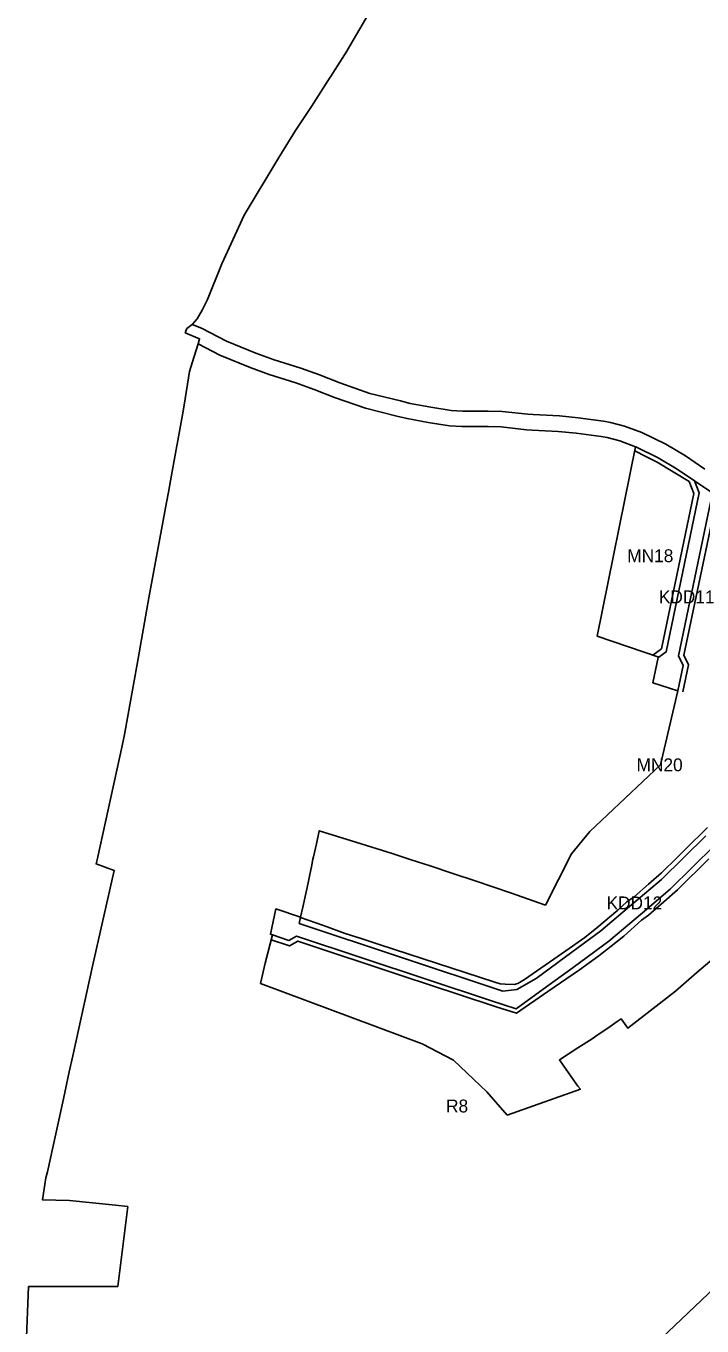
# Model space of a CAD drawing. Extents: x 7439486 to 7443435, y 5551288 to 5554556.
# Drawn here: x 7439611 to 7440135, y 5551897 to 5552904 of the extents above; entities that cross this region are included whole.
import ezdxf

# ---------------------------------------------------------------- set-up
doc = ezdxf.new("R2010")
doc.units = 0
for name, color, linetype in [('linie_rozgraniczajace', 7, 'Continuous'), ('linie_zabudowy_nieprzekraczalne', 7, 'Continuous'), ('oznaczenia_przeznaczen', 7, 'Continuous')]:
    doc.layers.add(name, color=color, linetype=linetype)

msp = doc.modelspace()

# ---------------------------------------------------------------- linework, layer by layer
at = {"layer": 'linie_rozgraniczajace'}
for points in [[(7439847.01, 5552864.42), (7439859.69, 5552884.24), (7439864.7, 5552892.84), (7439864.72, 5552892.88), (7439879.41, 5552917.8)], [(7440136.75, 5552560.73), (7440121.83, 5552570.88), (7440106.57, 5552579.91), (7440088.11, 5552589.02), (7440074.72, 5552593.93), (7440063.78, 5552596.91), (7440058.54, 5552597.78), (7440038.73, 5552600.51), (7440024.24, 5552601.88), (7440003.94, 5552602.96), (7439999.88, 5552603.17), (7439979.98, 5552605.4), (7439969.18, 5552605.67), (7439949.17, 5552605.61), (7439940.51, 5552606.18), (7439924.74, 5552608.72), (7439908.84, 5552611.58), (7439901.28, 5552613.47), (7439877.57, 5552619.38), (7439854.38, 5552627.4), (7439838.6, 5552633.66), (7439824.12, 5552638.78), (7439803.55, 5552645.29), (7439789.3, 5552650.49), (7439766.62, 5552659.73), (7439747.13, 5552669.92), (7439740.09, 5552672.71), (7439740.25, 5552672.84), (7439743.95, 5552677.01), (7439747.68, 5552683.73), (7439751.79, 5552692.12), (7439762.9, 5552719.61), (7439780.21, 5552757.37), (7439807.09, 5552802.1), (7439820.12, 5552822.79), (7439832.42, 5552841.4), (7439846.87, 5552864.2), (7439847.01, 5552864.42)], [(7439734.52, 5552666.24), (7439735.82, 5552669.57), (7439740.09, 5552672.71), (7439747.13, 5552669.92), (7439766.62, 5552659.73), (7439789.3, 5552650.49), (7439803.55, 5552645.29), (7439824.12, 5552638.78), (7439838.6, 5552633.66), (7439854.38, 5552627.4), (7439877.57, 5552619.38), (7439901.28, 5552613.47), (7439908.84, 5552611.58), (7439924.74, 5552608.72), (7439940.51, 5552606.18), (7439949.17, 5552605.61), (7439969.18, 5552605.67), (7439979.98, 5552605.4), (7439999.88, 5552603.17), (7440003.94, 5552602.96), (7440024.24, 5552601.88), (7440038.73, 5552600.51), (7440058.54, 5552597.78), (7440063.78, 5552596.91), (7440074.72, 5552593.93), (7440088.11, 5552589.02), (7440106.57, 5552579.91), (7440121.83, 5552570.88), (7440136.75, 5552560.73)], [(7440003.3, 5552590.98), (7439998.89, 5552591.21), (7439979.16, 5552593.42), (7439969.04, 5552593.67), (7439948.79, 5552593.61), (7439939.16, 5552594.24), (7439922.72, 5552596.89), (7439906.32, 5552599.84), (7439898.37, 5552601.83), (7439874.16, 5552607.87), (7439850.21, 5552616.15), (7439834.38, 5552622.42), (7439820.31, 5552627.4), (7439799.69, 5552633.93), (7439784.98, 5552639.29), (7439761.56, 5552648.83), (7439744.57, 5552657.73), (7439745.81, 5552661.68), (7439734.52, 5552666.24)], [(7439611.4, 5551881.93), (7439613.43, 5551927.75), (7439682.55, 5551927.9), (7439690.17, 5551989.77), (7439680.8, 5551990.73), (7439662.93, 5551992.58), (7439645.07, 5551994.44), (7439634.57, 5551994.74), (7439624.07, 5551995.04), (7439626.62, 5552011.92), (7439628.11, 5552016.58), (7439640.32, 5552073.23), (7439644.91, 5552094.13), (7439647.6, 5552106.42), (7439662.83, 5552175.92), (7439679.7, 5552250.02), (7439665.66, 5552255.08), (7439666.38, 5552258.33), (7439685.87, 5552346.55), (7439687.52, 5552355.35), (7439695.23, 5552396.78), (7439697.5, 5552409.68), (7439706.53, 5552461.04), (7439720.23, 5552534.81), (7439721.71, 5552542.98), (7439724.05, 5552555.91), (7439732.52, 5552602.7), (7439733.73, 5552610.29), (7439737.83, 5552636.3), (7439739.94, 5552642.98), (7439744.57, 5552657.73), (7439761.56, 5552648.83), (7439784.98, 5552639.29), (7439799.69, 5552633.93), (7439820.31, 5552627.4), (7439834.38, 5552622.42), (7439850.21, 5552616.15), (7439874.16, 5552607.87), (7439898.37, 5552601.83), (7439906.32, 5552599.84), (7439922.72, 5552596.89), (7439939.16, 5552594.24), (7439948.79, 5552593.61), (7439969.04, 5552593.67), (7439979.16, 5552593.42), (7439998.89, 5552591.21), (7440003.3, 5552590.98), (7440023.35, 5552589.91), (7440037.34, 5552588.59), (7440056.74, 5552585.91), (7440061.21, 5552585.17), (7440071.07, 5552582.48), (7440083.31, 5552578.01), (7440053.45, 5552431.46), (7440101.21, 5552415.17), (7440100.84, 5552414.91), (7440096.73, 5552395.22), (7440115.87, 5552389.07), (7440102.66, 5552331.77), (7440047.9, 5552280.13), (7440033.63, 5552262.97), (7440023.56, 5552243.08), (7440013.5, 5552223.2), (7439986.34, 5552232.6), (7439959.17, 5552241.99), (7439941.77, 5552247.72), (7439924.36, 5552253.44), (7439909.59, 5552258.3), (7439894.81, 5552263.15), (7439866.59, 5552271.96), (7439838.36, 5552280.76), (7439836.16, 5552270.66), (7439833.95, 5552260.55), (7439833.52, 5552258.6), (7439832.28, 5552252.7), (7439831.05, 5552246.79), (7439830, 5552241.8), (7439828.96, 5552236.81), (7439825.6, 5552221.49), (7439823.94, 5552213.92), (7439804.85, 5552220.26), (7439800.54, 5552200.62), (7439802.1, 5552200.1), (7439800.37, 5552193.23), (7439796.55, 5552178.12), (7439792.97, 5552162.52), (7439917.99, 5552115.63), (7439942.23, 5552103.19), (7439968.1, 5552078.48)], [(7440140.66, 5552543.57), (7440128.82, 5552551.62), (7440115.4, 5552560.74), (7440100.85, 5552569.35), (7440083.38, 5552577.98), (7440083.31, 5552578.01), (7440071.07, 5552582.48), (7440061.21, 5552585.17), (7440056.74, 5552585.91), (7440037.34, 5552588.59), (7440023.35, 5552589.91), (7440003.3, 5552590.98)], [(7440137.55, 5552276.9), (7440103.24, 5552242.87), (7440082.02, 5552224.85), (7440056.44, 5552203.12), (7440028.96, 5552183.05), (7440006.17, 5552166.39), (7439991.42, 5552157.79), (7439980.56, 5552156.64), (7439822.86, 5552209.01), (7439823.94, 5552213.92), (7439825.6, 5552221.49), (7439828.96, 5552236.81), (7439830, 5552241.8), (7439831.05, 5552246.79), (7439832.28, 5552252.7), (7439833.52, 5552258.6), (7439833.95, 5552260.55), (7439836.16, 5552270.66), (7439838.36, 5552280.76), (7439866.59, 5552271.96), (7439894.81, 5552263.15), (7439909.59, 5552258.3), (7439924.36, 5552253.44), (7439941.77, 5552247.72), (7439959.17, 5552241.99), (7439986.34, 5552232.6), (7440013.5, 5552223.2), (7440023.56, 5552243.08), (7440033.63, 5552262.97), (7440047.9, 5552280.13), (7440102.66, 5552331.77), (7440115.87, 5552389.07), (7440119.99, 5552408.76), (7440116.42, 5552416.13), (7440141.53, 5552536.28)], [(7439792.97, 5552162.52), (7439796.55, 5552178.12), (7439800.37, 5552193.23), (7439802.1, 5552200.1), (7439814.85, 5552195.86), (7439820.7, 5552199.19), (7439971.81, 5552149.02), (7439990.73, 5552142.73), (7440011.65, 5552158.02), (7440034.86, 5552174.97), (7440062.64, 5552195.27), (7440088.5, 5552217.23), (7440110.01, 5552235.5), (7440144.47, 5552269.69)], [(7440144.47, 5552269.69), (7440110.01, 5552235.5), (7440088.5, 5552217.23), (7440062.64, 5552195.27), (7440034.86, 5552174.97), (7440011.65, 5552158.02), (7439990.73, 5552142.73), (7439971.81, 5552149.02), (7439820.7, 5552199.19), (7439814.85, 5552195.86), (7439802.1, 5552200.1), (7439800.54, 5552200.62), (7439804.85, 5552220.26), (7439823.94, 5552213.92), (7439822.86, 5552209.01), (7439980.56, 5552156.64), (7439991.42, 5552157.79), (7440006.17, 5552166.39), (7440028.96, 5552183.05), (7440056.44, 5552203.12), (7440082.02, 5552224.85), (7440103.24, 5552242.87), (7440137.55, 5552276.9)], [(7439968.1, 5552078.48), (7439983.87, 5552060.52), (7440040.55, 5552080.59), (7440038.52, 5552082.98), (7440033.13, 5552090.69), (7440027.74, 5552098.4), (7440024.32, 5552103.35), (7440038.68, 5552112.6), (7440049.66, 5552119.66), (7440054.38, 5552122.93), (7440061.69, 5552127.98), (7440069.07, 5552133.08), (7440070.59, 5552134.13), (7440072.05, 5552135.14), (7440077.2, 5552127.96), (7440114.09, 5552156.56), (7440130.74, 5552170.86), (7440147.39, 5552185.16)], [(7440147.39, 5552185.16), (7440130.74, 5552170.86), (7440114.09, 5552156.56), (7440077.2, 5552127.96), (7440072.05, 5552135.14), (7440070.59, 5552134.13), (7440069.07, 5552133.08), (7440061.69, 5552127.98), (7440054.38, 5552122.93)], [(7440054.38, 5552122.93), (7440049.66, 5552119.66), (7440038.68, 5552112.6), (7440024.32, 5552103.35), (7440027.74, 5552098.4), (7440033.13, 5552090.69), (7440038.52, 5552082.98), (7440040.55, 5552080.59), (7439983.87, 5552060.52), (7439968.1, 5552078.48), (7439942.23, 5552103.19), (7439917.99, 5552115.63), (7439792.97, 5552162.52)], [(7440170.49, 5551951.58), (7439741.39, 5551543.86)], [(7439741.39, 5551543.86), (7440170.49, 5551951.58)]]:
    msp.add_lwpolyline(points, dxfattribs=at)
for points in [[(7440053.45, 5552431.46), (7440083.31, 5552578.01), (7440083.38, 5552577.98), (7440100.85, 5552569.35), (7440115.4, 5552560.74), (7440128.82, 5552551.62), (7440132.57, 5552542.31), (7440106.86, 5552419.23), (7440101.21, 5552415.17)], [(7440096.73, 5552395.22), (7440100.84, 5552414.91), (7440101.21, 5552415.17), (7440106.86, 5552419.23), (7440132.57, 5552542.31), (7440128.82, 5552551.62), (7440140.66, 5552543.57), (7440147.73, 5552538.77), (7440141.53, 5552536.28), (7440116.42, 5552416.13), (7440119.99, 5552408.76), (7440115.87, 5552389.07)]]:
    msp.add_lwpolyline(points, close=True, dxfattribs=at)
at = {"layer": 'linie_zabudowy_nieprzekraczalne'}
for points in [[(7440096.56, 5552416.75), (7440103.26, 5552421.57), (7440128.41, 5552541.94), (7440124.68, 5552551.18), (7440099.97, 5552566), (7440091.29, 5552570.4), (7440082.62, 5552574.8)], [(7440145, 5552533.36), (7440120.61, 5552416.65), (7440124.18, 5552409.28), (7440119.79, 5552388.25)], [(7439823.88, 5552213.66), (7439841.59, 5552207.25), (7439858.47, 5552201.14), (7439871.68, 5552196.94), (7439884.89, 5552192.75), (7439974.31, 5552163.44), (7439978.46, 5552162.25), (7439982.21, 5552161.87), (7439989.23, 5552161.56), (7439992, 5552162.53), (7439997.27, 5552165.6), (7440013.32, 5552176.64), (7440029.38, 5552187.69), (7440043.87, 5552198.14), (7440053.15, 5552205.47), (7440069.45, 5552219.25), (7440076.47, 5552225.7), (7440082.24, 5552229.66), (7440093.18, 5552239.24), (7440103.33, 5552248.22), (7440115.32, 5552260.01), (7440127.31, 5552271.8), (7440133.19, 5552277.51), (7440139.03, 5552283.16)], [(7440139.93, 5552258.97), (7440115.61, 5552235.05), (7440105.07, 5552225.73), (7440093.3, 5552215.43), (7440087.71, 5552211.59), (7440074.12, 5552199.1), (7440064.42, 5552191.43), (7440054.72, 5552183.77), (7440039.74, 5552172.98), (7440015.39, 5552156.21), (7439991.03, 5552139.45), (7439975.23, 5552144.32), (7439946.46, 5552153.92), (7439903.33, 5552168.13), (7439821.86, 5552195.25), (7439815.28, 5552191.51), (7439801.12, 5552196.21)]]:
    msp.add_lwpolyline(points, dxfattribs=at)

# ---------------------------------------------------------------- texts
at = {"layer": 'oznaczenia_przeznaczen'}
for s, p in [('MN18', (7440076.81, 5552488.65)), ('KDD11', (7440101.28, 5552456.81)), ('MN20', (7440084.04, 5552326.77)), ('KDD12', (7440060.76, 5552219.85)), ('R8', (7439936.56, 5552062.63))]:
    msp.add_text(s, height=10, dxfattribs=at).set_placement(p)

doc.saveas('drawing.dxf')
